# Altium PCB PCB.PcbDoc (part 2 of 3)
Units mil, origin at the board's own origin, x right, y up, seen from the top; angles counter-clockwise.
Board outline 3613 x 4415 mil, 2 copper layers (Top Layer, Bottom Layer), stack 62 mil thick; 332 components, 200 nets, 890 pads, 1069 vias.
Unrouted connection lines stored in the file: 1.
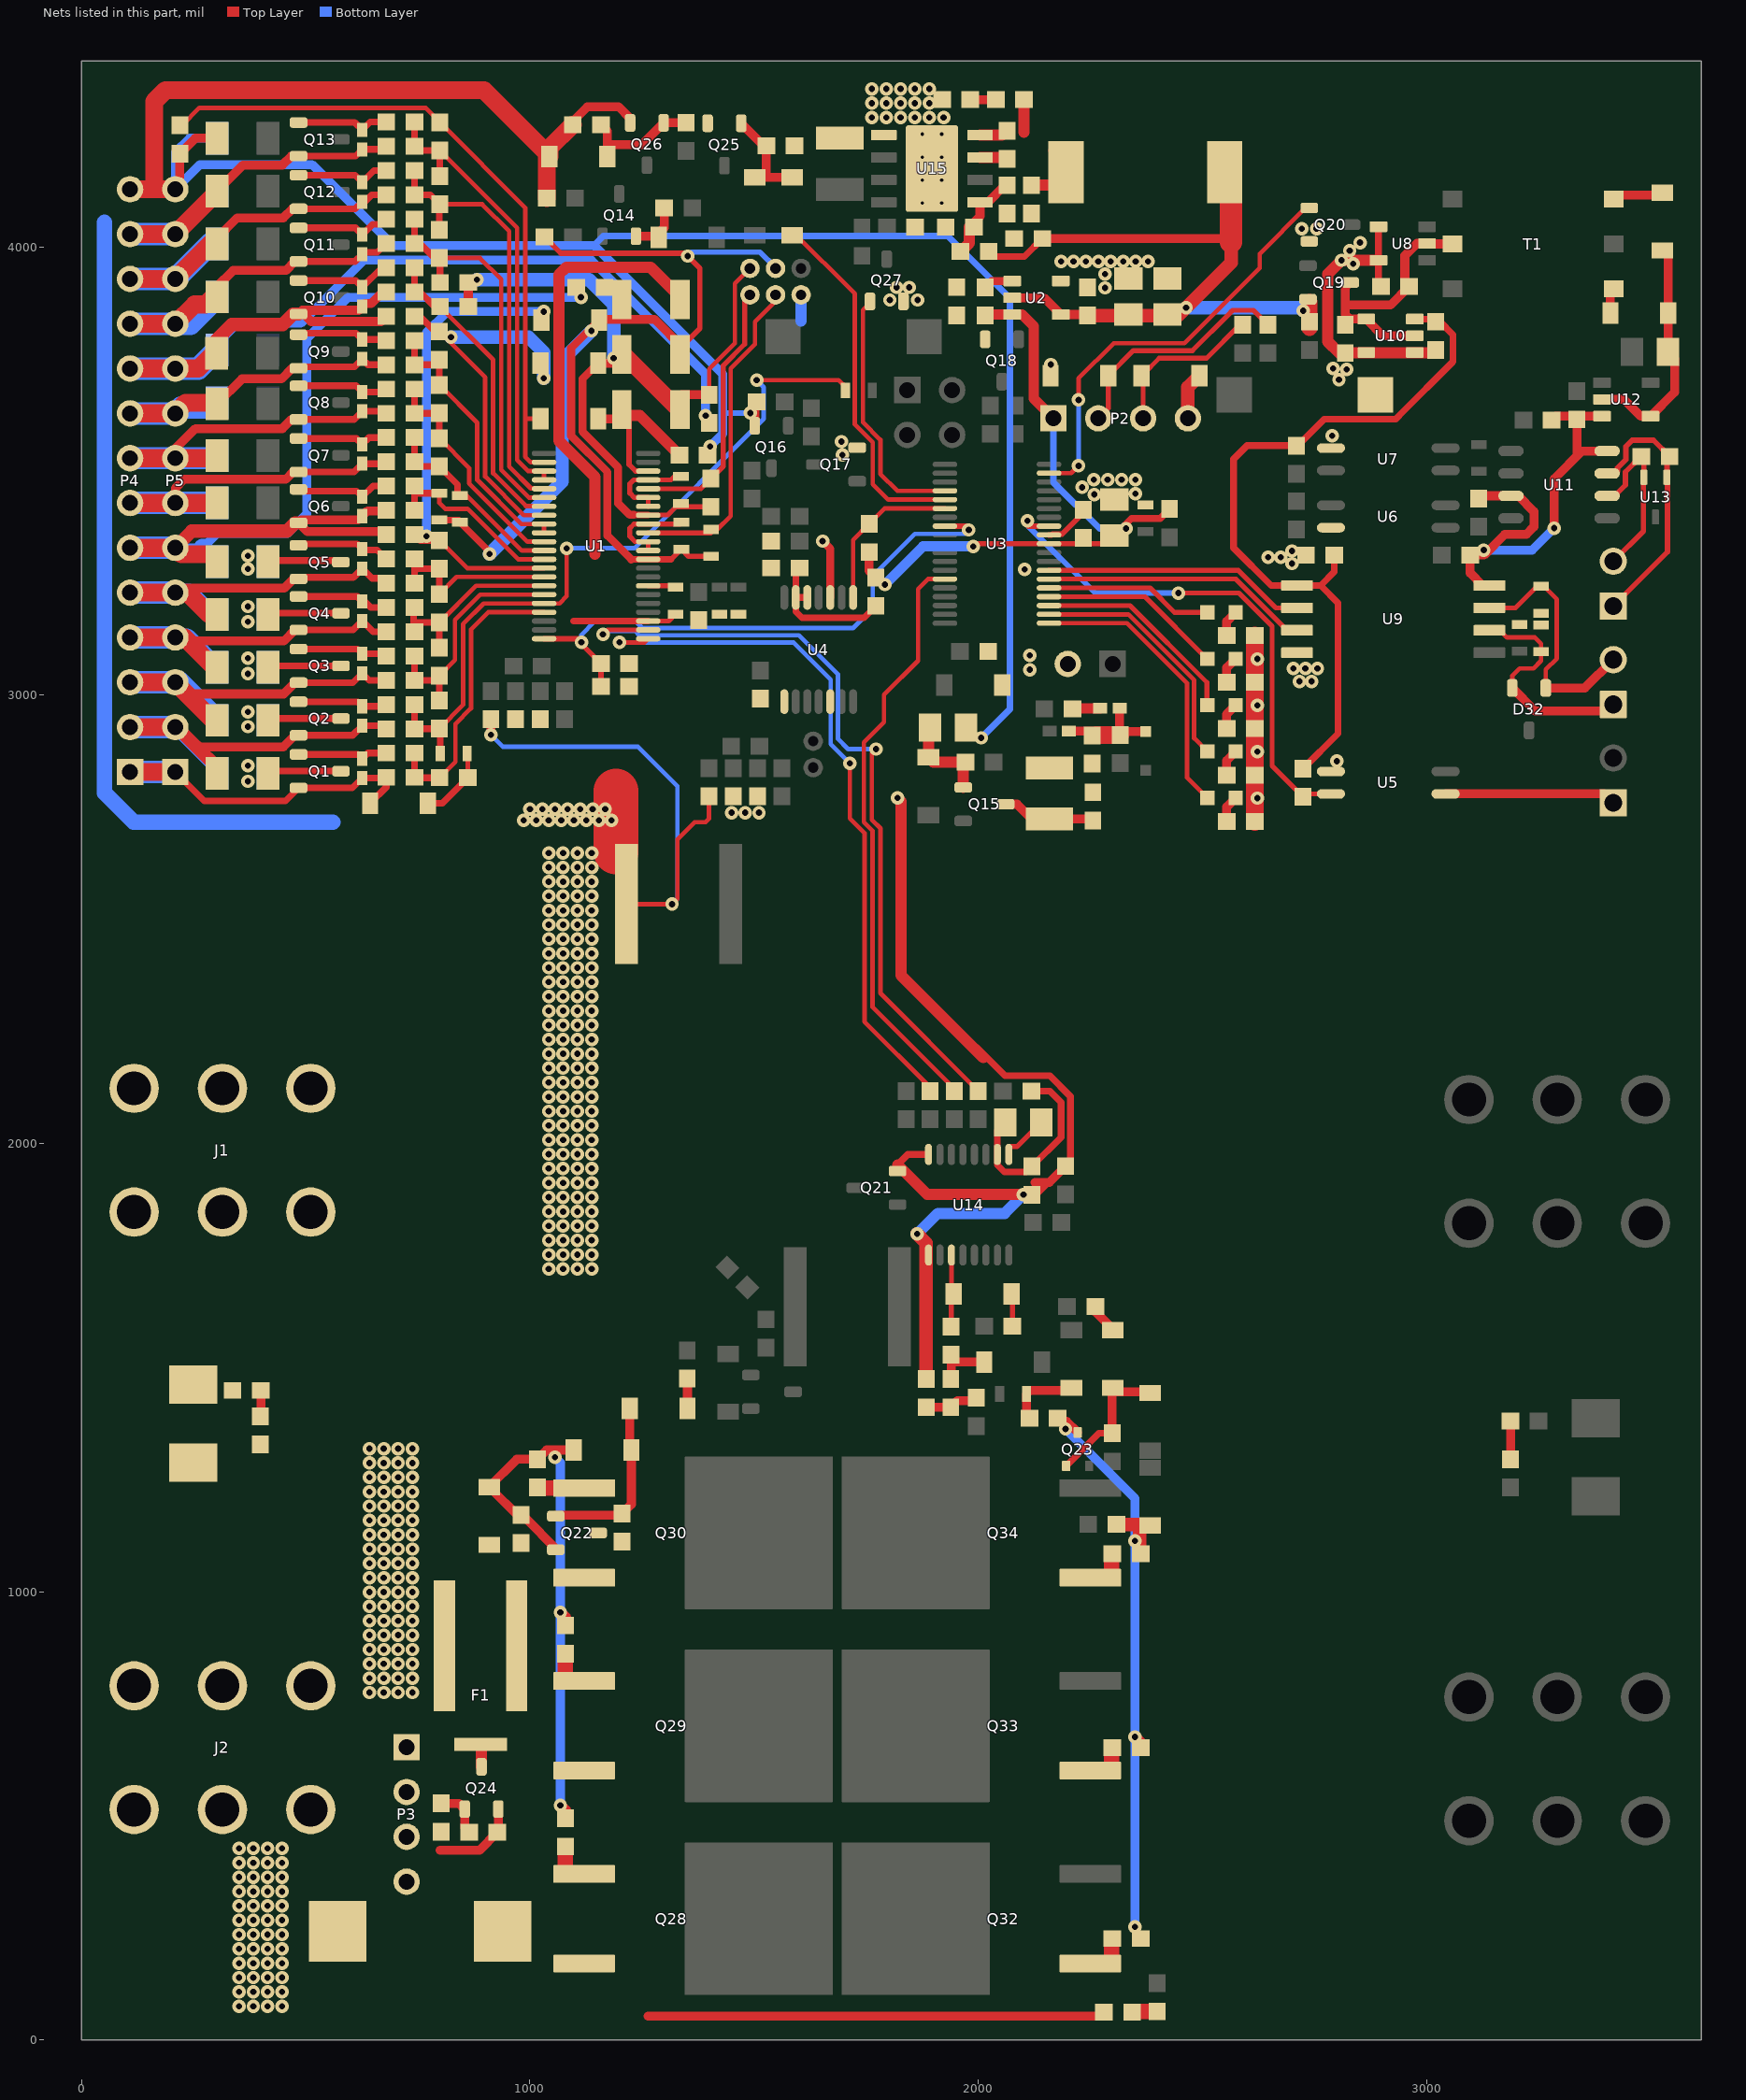
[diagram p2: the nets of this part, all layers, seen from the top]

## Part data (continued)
R11 R12 R13 R14 R15 R16 R30 R31 R32 R33 R34 R50 R51 R52 R53 R54 R63 R64 R65 R95 R96 R97 R99: "RES, 1.00 k, 1%, 0.1 W, 0603", Manufacturer=Vishay-Dale, Power_W=0.1, Supplier Part Number 1=541-1.00KHCT-ND, TempCo="100 ppm/C", Tolerance_%=1, Value1=1%, Value2=0.1W, Value_Code=1k00, ValueDisplayed=1.00k
R17 R18 R19 R20 R21 R35 R36 R37 R38 R55 R56 R57 R58 R66: "RES, 10 k, 5%, 0.1 W, 0603", Manufacturer=Vishay-Dale, Power_W=0.1, Supplier Part Number 1=541-10KGCT-ND, TempCo="200 ppm/C", Tolerance_%=5, Value1=5%, Value2=0.1W, Value_Code=10k0, ValueDisplayed=10k
R47 R49 R87: "RES, 100 k, 1%, 0.1 W, 0603", Manufacturer=Vishay-Dale, Power_W=0.1, Supplier Part Number 1=541-100KHCT-ND, TempCo="100 ppm/C", Tolerance_%=1, Value1=1%, Value2=0.1W, Value_Code=100k
R48 R100: "RES, 200, 1%, 0.1 W, 0603", Manufacturer=Vishay-Dale, Power_W=0.1, Supplier Part Number 1=541-200HCT-ND, TempCo="100 ppm/C", Tolerance_%=1, Value1=1%, Value2=0.1W, Value_Code=200R, ValueDisplayed=200
R59 R69 R106 R112: "RES, 1.0 M, 5%, 0.1 W, 0603", Manufacturer=Vishay-Dale, Power_W=0.1, Supplier Part Number 1=541-1.0MGCT-ND, TempCo="200 ppm/C", Tolerance_%=5, Value1=5%, Value2=0.1W, Value_Code=1M00, ValueDisplayed=1.0M
R60: "RES, 499 k, 1%, 0.1 W, 0603", Manufacturer=Vishay-Dale, Power_W=0.1, Supplier Part Number 1=541-499KHCT-ND, TempCo="100 ppm/C", Tolerance_%=1, Value1=1%, Value2=0.1W, Value_Code=499k
R61 R84 R85 R98 R107 R108 R111 R113 R117 R120 R124 R127: "RES, 100, 1%, 0.1 W, 0603", Manufacturer=Vishay-Dale, Power_W=0.1, Supplier Part Number 1=541-100HCT-ND, TempCo="100 ppm/C", Tolerance_%=1, Value1=1%, Value2=0.1W, Value_Code=100R, ValueDisplayed=100
R62 R103 R105 R110 R114 R121: "RES, 10 M, 5%, 0.1 W, 0603", Manufacturer=Vishay-Dale, Power_W=0.1, Supplier Part Number 1=541-10MGCT-ND, TempCo="200 ppm/C", Tolerance_%=5, Value1=5%, Value2=0.1W, Value_Code=10M0, ValueDisplayed=10M
R67: "RES, 360 k, 1%, 0.1 W, AEC-Q200 Grade 0, 0603", Manufacturer=Panasonic, Power_W=0.1, Supplier Part Number 1=P360KHCT-ND, TempCo="100 ppm/C", Tolerance_%=1, Value1=1%, Value2=0.1W, Value_Code=360k
R68: "RES, 3.01 k, 1%, 0.1 W, 0603", Manufacturer=Vishay-Dale, Power_W=0.1, Supplier Part Number 1=541-3.01KHCT-ND, TempCo="100 ppm/C", Tolerance_%=1, Value1=1%, Value2=0.1W, Value_Code=3k01, ValueDisplayed=3.01k
R70 R104: "RES, 3.3 M, 5%, 0.1 W, 0603", Manufacturer=Vishay-Dale, Power_W=0.1, Supplier Part Number 1=541-3.3MGCT-ND, TempCo="200 ppm/C", Tolerance_%=5, Value1=5%, Value2=0.1W, Value_Code=3M30, ValueDisplayed=3.3M
R71 R72: "RES, 505 k, 0.1%, 0.1 W, 0603", Manufacturer="Yageo America", Power_W=0.1, TempCo="25 ppm/C", Value1=0.1%, Value2=0.1W, Value_Code=505k
R73 R102: "RES, 16.5 k, 0.1%, 0.1 W, 0603", Manufacturer="Yageo America", Power_W=0.1, TempCo="25 ppm/C", Value1=0.1%, Value2=0.1W, Value_Code=16k5, ValueDisplayed=16.5k
R74 R115: "RES, 47.0, 1%, 0.1 W, 0603", Manufacturer="Yageo America", Power_W=0.1, Supplier Part Number 1=311-47.0HRCT-ND, TempCo="200 ppm/C", Tolerance_%=1, Value1=1%, Value2=0.1W, Value_Code=47R0, ValueDisplayed=47.0
R75 R81 R83 R88 R89 R90 R91: "RES, 10.0 k, 1%, 0.1 W, 0603", Manufacturer=Vishay-Dale, Power_W=0.1, Supplier Part Number 1=541-10.0KHCT-ND, TempCo="100 ppm/C", Tolerance_%=1, Value1=1%, Value2=0.1W, Value_Code=10k0, ValueDisplayed=10.0k
R76 R77 R78 R79 R80: "RES, 470, 1%, 0.1 W, 0603", Manufacturer="Yageo America", Power_W=0.1, Supplier Part Number 1=311-470HRCT-ND, TempCo="200 ppm/C", Tolerance_%=1, Value1=1%, Value2=0.1W, Value_Code=470R, ValueDisplayed=470
R82: "RES, 47.0 k, 1%, 0.1 W, 0603", Manufacturer="Yageo America", Power_W=0.1, Supplier Part Number 1=311-47.0KHRCT-ND, TempCo="200 ppm/C", Tolerance_%=1, Value1=1%, Value2=0.1W, Value_Code=47k0, ValueDisplayed=47.0k
R86: "RES, 6.8 k, 5%, 0.1 W, 0603", Manufacturer=Vishay-Dale, Power_W=0.1, Supplier Part Number 1=541-6.8KGCT-ND, TempCo="200 ppm/C", Tolerance_%=5, Value1=5%, Value2=0.1W, Value_Code=6k80, ValueDisplayed=6.8k
R92 R93: "RES, 60.4, 1%, 0.1 W, 0603", Manufacturer="Yageo America", Power_W=0.1, Supplier Part Number 1=311-60.4HRCT-ND, TempCo="200 ppm/C", Tolerance_%=1, Value1=1%, Value2=0.1W, Value_Code=60R4, ValueDisplayed=60.4
R94: "RES, 120, 1%, 0.1 W, 0603", Manufacturer="Yageo America", Power_W=0.1, Supplier Part Number 1=311-120HRCT-ND, TempCo="200 ppm/C", Tolerance_%=1, Value1=1%, Value2=0.1W, Value_Code=120R, ValueDisplayed=120
R101: "RES, 665 k, 0.1%, 0.1 W, 0603", Manufacturer="Yageo America", Power_W=0.1, TempCo="25 ppm/C", Value1=0.1%, Value2=0.1W, Value_Code=665k
R109: "RES, 510, 5%, 0.1 W, 0603", Manufacturer=Vishay-Dale, Power_W=0.1, Supplier Part Number 1=541-510GCT-ND, TempCo="200 ppm/C", Tolerance_%=5, Value1=5%, Value2=0.1W, Value_Code=510R, ValueDisplayed=510
R116: "RES, 2.49 M, 1%, 0.1 W, 0603", Manufacturer=Vishay-Dale, Power_W=0.1, Supplier Part Number 1=541-2.49MHCT-ND, TempCo="100 ppm/C", Tolerance_%=1, Value1=1%, Value2=0.1W, Value_Code=2M49, ValueDisplayed=2.49M
R118 R119: "RES, 0.002, 1%, 2 W, 2512", Manufacturer="Stackpole Electronics Inc", Power_W=2, Supplier Part Number 1=CSNL2512FT2L00CT-ND, TempCo="50 ppm/C", Tolerance_%=1, Value1=1%, Value2=2W, Value_Code=2L000, ValueDisplayed=0.002
R122: "RES, 6.8 M, 5%, 0.1 W, 0603", Manufacturer=Vishay-Dale, Power_W=0.1, Supplier Part Number 1=541-6.8MGCT-ND, TempCo="200 ppm/C", Tolerance_%=5, Value1=5%, Value2=0.1W, Value_Code=6M80, ValueDisplayed=6.8M
R123: "RES, 3.0 M, 5%, 0.1 W, 0603", Manufacturer=Vishay-Dale, Power_W=0.1, Supplier Part Number 1=541-3.0MGCT-ND, TempCo="200 ppm/C", Tolerance_%=5, Value1=5%, Value2=0.1W, Value_Code=3M00, ValueDisplayed=3.0M
R125: "RES, 1.00 M, 1%, 0.1 W, 0603", Manufacturer=Vishay-Dale, Power_W=0.1, Supplier Part Number 1=541-1.00MHCT-ND, TempCo="100 ppm/C", Tolerance_%=1, Value1=1%, Value2=0.1W, Value_Code=1M00, ValueDisplayed=1.00M
R126: "RES, 115 k, 1%, 0.1 W, 0603", Manufacturer=Vishay-Dale, Power_W=0.1, Supplier Part Number 1=541-115KHCT-ND, TempCo="100 ppm/C", Tolerance_%=1, Value1=1%, Value2=0.1W, Value_Code=115k
R128: "NC", Manufacturer="Yageo America", Power_W=0.1, Supplier Part Number 1=311-383KHRCT-ND, TempCo="200 ppm/C", Tolerance_%=1, Value1=1%, Value2=0.1W, Value_Code=383k
R129: "RES, 383 k, 1%, 0.1 W, 0603", Manufacturer="Yageo America", Power_W=0.1, Supplier Part Number 1=311-383KHRCT-ND, TempCo="200 ppm/C", Tolerance_%=1, Value1=1%, Value2=0.1W, Value_Code=383k
R130: "RES, 240 k, 5%, 0.1 W, 0603", Manufacturer=Vishay-Dale, Power_W=0.1, Supplier Part Number 1=541-240KGCT-ND, TempCo="200 ppm/C", Tolerance_%=5, Value1=5%, Value2=0.1W, Value_Code=240k
R131: "RES, 715 k, 1%, 0.1 W, 0603", Manufacturer=Vishay-Dale, Power_W=0.1, Supplier Part Number 1=541-715KHCT-ND, TempCo="100 ppm/C", Tolerance_%=1, Value1=1%, Value2=0.1W, Value_Code=715k
R132 R133: "RES, 604, 1%, 1 W, AEC-Q200 Grade 0, 2512", Manufacturer=Vishay-Dale, Power_W=1, Supplier Part Number 1=541-604AFCT-ND, TempCo="100 ppm/C", Value1=1%, Value2=1W, Value_Code=604R, ValueDisplayed=604
RT1 RT2 RT3 RT4: "Thermistor NTC, 10k ohm, 2%, NTC Thermistor, Mini Lug Sensor, Pitch 1.5mm", Manufacturer=Vishay-Bccomponents, Power_W=0.1, Supplier Part Number 1=BC2385-ND, Tolerance_%=2
S1 S2: "Switch, Tactile, SPST-NO, 0.05A, 12V, SMD", CurrentRating_mA=50, Manufacturer="C&K Components", Supplier Part Number 1=CKN10388CT-ND
T1: "Transformer, 475 uH, SMT", Manufacturer="Wurth Elektronik", Supplier Part Number 1=732-4456-1-ND, ValueDisplayed=475μH
U1: library part CMP-0065910-1, "9 to 15-Series Cell Li-Ion and Li-Phosphate Battery Monitor (bq76940 Family), DBT0044A (TSSOP-44)", Alternate Manufacturer="Texas Instruments", Alternate PartNumber=BQ7694003DBT
U2 U10: "Single Output LDO, 150 mA, Fixed 3.3 V Output, 2.5 to 24 V Input, with Ultra-Low IQ, 5-pin SOT-23 (DBV), -40 to 125 degC, Green (RoHS & no Sb/Br)", Alternate Manufacturer="Texas Instruments", Alternate PartNumber=Equivalent, Supplier Part Number 1=TLV70433DBVR-ND
U3: library part CMP-0084060-1, "24MHz 105C ULP Microcontroller With 32 KB FRAM, 4 KB SRAM, 44 IO, 12-bit ADC, DBT0038A (TSSOP-38)", Alternate Manufacturer="Texas Instruments", Alternate PartNumber=MSP430FR2155TDBT, Operating Temperature Range="-40 to 105 C", Rating=Catalog
U4: library part CMP-0082025-1, "Multi-Chemistry Impedance Track Standalone Fuel Gauge", Alternate Manufacturer="Texas Instruments", Alternate PartNumber=BQ34Z100PW-G1, Operating Temperature Range="-40 to 85 C"
U5 U6 U7: "Optocoupler, 3.75 kV, 100-600% CTR, SMT", Manufacturer=Toshiba, Supplier Part Number 1=TLP293(GB-TPLECT-ND, Voltage_Isolation_Vrms=3750V
U8: library part CMP-0065840-1, "Low-Noise 350 mA, 410 kHz Transformer Driver, DBV0005A (SOT-23-5)", Alternate Manufacturer="Texas Instruments", Alternate PartNumber=SN6501DBVT
U9: library part CMP-0077952-1, "Reinforced Isolated CAN XCVRs with 70V Protection Voltage and CAN FD, DWV0008A (SOIC-8)", Alternate Manufacturer="Texas Instruments", Alternate PartNumber=ISO1042BDWV
U11: library part CMP-0013008-2, "250 kbps RS-485 Transceivers With +/-12-kV IEC ESD Protection, D0008A (SOIC-8)", Alternate Manufacturer="Texas Instruments", Alternate PartNumber=THVD1500D
U12: "Single Output LDO, 150 mA, Fixed 5 V Output, 2.5 to 24 V Input, with Ultra-Low IQ, 5-pin SOT-23 (DBV), -40 to 125 degC, Green (RoHS & no Sb/Br)", Alternate Manufacturer="Texas Instruments", Alternate PartNumber=Equivalent, Supplier Part Number 1=296-28171-2-ND
U13: "ESD Protection Array for AC Signal Data Interface, 2 Channels, -40 to +85 degC, 3-pin SC70 (DCK), Green (RoHS & no Sb/Br)", Alternate Manufacturer="Texas Instruments", Alternate PartNumber=Equivalent, Breakdown Voltage(Min)(V)=+/-14, IO Capacitance(Typ)(pF)=15, IO Leakage Current(nA)=50, Supplier Part Number 1=296-25281-2-ND
U14: library part CMP-0076175-1, "High-Side N-Channel FET Driver, PW0016A (TSSOP-16)", Alternate Manufacturer="Texas Instruments", Alternate PartNumber=BQ76200PW
U15: library part CMP-0080798-1, "100-V Low IQ Synchronous Buck Regulator, DDA0008E (SOIC-8)", Alternate Manufacturer="Texas Instruments"

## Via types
v1: diameter 30, hole 14, Top Layer to Bottom Layer, 1060 vias
v2: diameter 19.68, hole 7.87, Top Layer to Bottom Layer, tented both sides, 4 vias
v3: diameter 19.68, hole 7.87, Top Layer to Bottom Layer, 4 vias
v4: diameter 30, hole 14, Top Layer to Bottom Layer, tented bottom, 1 vias

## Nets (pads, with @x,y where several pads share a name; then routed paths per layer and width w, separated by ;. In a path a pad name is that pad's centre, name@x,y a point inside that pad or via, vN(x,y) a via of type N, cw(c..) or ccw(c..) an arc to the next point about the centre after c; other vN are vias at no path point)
3V3: C31.2 C33.2 C34.1 C35.1 P2.1 Q18.2 R74.1 R75.1 R82.2 U2.3 U3.10 | length 1424.5
  Top Layer w12: v1@1992,3338 U3.10@2158.14,3338 C31.2@2285.55,3338
  Top Layer w15: C31.2@2304,3356.45 2342.18,3394.63 2406.13,3394.63 R82.2@2427,3415.5
  Top Layer w20: R75.1@1757,3319.5 1757,3277.5 R74.1@1772,3262.5
  Top Layer w23: C34.1@2018.24,3849.6 U2.3@2076,3849.6 2098,3849.6 2124,3823.6 2124,3662 P2.1@2168,3618
  Bottom Layer w15: P2.1@2168,3618 2168,3475 2271,3372 v1(2330,3372)
  Bottom Layer w23: v1(1792,3247) 1877,3332 v1(1989,3332)
3V3_Com: C39.2 C44.1 R88.2 R89.2 U9.1 U10.3 | length 1695.2
  Top Layer w15: R89.2@2725,2836.5 2803,2914.5 2803,3206 2764,3245 ; C39.2@2794.5,3313 2794.5,3275.5 2764,3245 ; U10.3@2974.13,3839.4 C44.1@3015.09,3839.4 ; C44.1@3021,3833.5 3030.5,3833.5 3059,3805 3059,3744 2939.35,3624.35 2939.35,3624.04 2931.44,3616.13 2931.13,3616.13 2931,3616 2772,3616 2713,3557 R88.2@2710,3557 2600,3557 2570,3527 2570,3329 2654,3245 U9.1@2711.43,3245 2764,3245
5V: C32.1 C65.2 C66.1 C67.1 L1.2 Q19.2 R87.1 R131.2 U2.2 U2.4 | length 1622.8
  Top Layer w15: R131.2@2034.5,3979 2103.5,3979 C65.2@2143.5,4019
  Top Layer w20: U2.2@2076,3887 2146.87,3887 U2.4@2184.27,3849.6 2241.54,3849.6 C32.1@2244,3847.14 ; C65.2@2143.5,4019 2556.54,4019
  Top Layer w30: C32.1@2244,3847.14 2446.14,3847.14 v1(2464,3865) 2564.27,3965.27 2564.27,4011.27
  Top Layer w35: R87.1@2739,3819 R87.1@2739,3833.5 Q19.2@2739,3878
  Top Layer w50: L1.2@2550.17,4167 2564.27,4152.89 2564.27,4011.27
  Bottom Layer w30: v1(2464,3865) 2718,3865 v1(2725,3858)
5V_S: C41.1 C43.1 C47.1 R90.2 U9.8 U11.3 U11.8 U12.3 | length 1062.2
  Top Layer w20: R90.2@3117,3439 3123,3445 U11.3@3188.72,3445 3205,3445 3240,3410 3240,3376 3223,3359 3175,3359 3129,3313 C43.1@3097.5,3313 3097.5,3272.61 3125.11,3245 U9.8@3140.57,3245 ; C41.1@3279.5,3614 3288.09,3622.6 U12.3@3391.87,3622.6 ; v1(3285,3373) 3285,3483 3347,3545 U11.8@3403.28,3545 ; 3336,3538 C47.1@3336,3615.5
  Bottom Layer w20: v1(3128,3324) 3236,3324 v1(3285,3373)
430_Power: D45.2 U3.24 | length 833.7
  Top Layer w10: D45.2@1585,4017 1585,4035.88 1725,3895.88 1725,3604 1754.32,3574.69 1754.6,3574.69 1765,3564.28 1765,3471 1799.57,3436.43 U3.24@1925.86,3436.43
485A: J3.2 R94.2 U11.6 U13.2 | length 385.6
  Top Layer w12: U11.6@3403.28,3445 3420.02,3445 3444.05,3469.03 3444.05,3498.05 3479,3533 R94.2@3479.5,3533 ; J3.2@3417,3299 3484,3366 3484,3484.88 U13.2@3485.41,3486.29 R94.2@3485.41,3526.59
485B: J3.1 R94.1 U11.7 U13.1 | length 585.2
  Top Layer w12: U11.7@3403.28,3495 3422,3495 3426.05,3499.05 3426.05,3507.05 3445,3526 3445,3555 3459,3569 3506.5,3569 R94.1@3542.5,3533 ; J3.1@3417,3199 3538,3320 3538,3484.88 U13.1@3536.59,3486.29 R94.1@3536.59,3527.09
ALERT: C19.1 R60.2 U1.44 U3.27 | length 1295.6
  Top Layer w12: U1.44@1031.69,3126.18 1106.82,3126.18 v1(1115,3118) 1115,3114.5 C19.1@1158.5,3071 R60.2@1158.5,3020 ; U3.27@1925.86,3377.37 1976.37,3377.37 1977,3378 1979,3376 v1(1979,3369)
  Bottom Layer w10: v1(1115,3118) 1115,3135 1144,3164 1236.63,3164 1250.63,3150 1721,3150 1765,3194 1765,3266 1859,3360 1970,3360 v1(1979,3369)
Alert_Gauge: R75.2 U3.25 U4.1 | length 362.2
  Top Layer w10: U4.1@1721.17,3218.17 1721.17,3346.67 R75.2@1757,3382.5 1791.24,3416.74 U3.25@1925.86,3416.74
BAT: C26.2 D20.1 R65.2 U1.20 | length 365.6
  Top Layer w12: C26.2@1221,3621.04 1221,3515 1235.81,3500.19 U1.20@1263.98,3500.19
  Top Layer w20: D20.1@1152.47,3617 C26.2@1208.91,3617
  Top Layer w25: C26.2@1216,3624.09 1245.42,3624.09 R65.2@1333.5,3536
BAT+: C53.1 D44.1 F1.1 F2.2 J2.1 J2.2 J2.3 J2.4 J2.5 J2.6
  other v1: 351,75 383,75 415,75 447,75 351,107 383,107 415,107 447,107 351,139 383,139 415,139 447,139 351,171 383,171 415,171 447,171 351,203 383,203 415,203 447,203 351,235 383,235 415,235 447,235 351,267 383,267 415,267 447,267 351,299 383,299 415,299 447,299 351,331 383,331 415,331 447,331 351,363 383,363 415,363 447,363 351,395 383,395 415,395 447,395 351,427 383,427 415,427 447,427 642,775 674,775 706,775 738,775 642,807 674,807 706,807 738,807 642,839 674,839 706,839 738,839 642,871 674,871 706,871 738,871 642,903 674,903 706,903 738,903 642,935 674,935 706,935 738,935 642,967 674,967 706,967 738,967 642,999 674,999 706,999 738,999 642,1031 674,1031 706,1031 738,1031 642,1063 674,1063 706,1063 738,1063 642,1095 674,1095 706,1095 738,1095 642,1127 674,1127 706,1127 738,1127 642,1159 674,1159 706,1159 738,1159 642,1191 674,1191 706,1191 738,1191 642,1223 674,1223 706,1223 738,1223 642,1255 674,1255 706,1255 738,1255 642,1287 674,1287 706,1287 738,1287 642,1319 674,1319 706,1319 738,1319
C0: C1.1 R11.2 R17.2 U1.41 | length 649.3
  Top Layer w10: C1.1@798.5,2816 834,2851.5 834,2936.23 868.75,2970.97 868.75,3146.75 907.23,3185.23 U1.41@1031.69,3185.23
  Top Layer w15: R17.2@742.5,2871.05 R11.2@742.5,2816.91 743.41,2816 C1.1@798.5,2816
C1: C2.1 C3.2 R12.2 R18.2 R68.2 U1.40 | length 1645.1
  Top Layer w10: C3.2@798,2925.5 850.87,2978.38 850.87,3158.87 896.92,3204.92 U1.40@1031.69,3204.92 1065.92,3204.92 1082,3221 v1(1082,3328) ; v1(1506,3703) 1689,3703 R68.2@1704,3688
  Top Layer w15: R18.2@742.5,2979.35 R12.2@742.5,2925.2 798.3,2925.2 800,2923.5 C2.1@800,2870
  Bottom Layer w10: v1@1082,3324 v1(1082,3328) 1233,3328 1521.5,3616.5 1521.5,3687.5 v1(1506,3703)
C2: C3.1 C4.2 R13.2 R19.2 U1.39 | length 529.9
  Top Layer w10: C4.2@798,3043.5 833,3078.5 833,3168 889.6,3224.6 U1.39@1031.69,3224.6
  Top Layer w15: R19.2@742.5,3087.65 R13.2@742.5,3033.5 788,3033.5 C4.2@798,3043.5 C3.1@798,2988.5
C3: C4.1 C5.2 R14.2 R20.2 U1.38 | length 412.5
  Top Layer w10: C5.2@798,3162.5 879.78,3244.29 U1.38@1031.69,3244.29
  Top Layer w15: R20.2@740.5,3193.94 740.5,3162.5 C5.2@798,3162.5 C4.1@798,3106.5
C4: C5.1 C6.2 R15.2 R21.2 U1.37 | length 418.8
  Top Layer w10: C5.1@798,3225.5 836.48,3263.97 U1.37@1031.69,3263.97
  Top Layer w15: R15.2@742.5,3250.09 742.5,3276.5 ; R21.2@742.5,3304.24 742.5,3276.5 ; C5.1@798,3225.5 C6.2@798,3282.5 748.5,3282.5 742.5,3276.5
C5: C6.1 D17.2 R16.2 U1.36 | length 1062
  Top Layer w10: C6.1@798,3345.5 859.84,3283.66 U1.36@1031.69,3283.66
  Top Layer w15: R16.2@742.5,3358.39 755.39,3345.5 C6.1@798,3345.5
  Top Layer w20: C6.1@798,3345.5 C6.1@802.5,3350
  Bottom Layer w20: v1(769,3355) 769,3809 814,3854 816,3856 v1(1031,3856)
C5B: C7.1 R30.2 R35.2 U1.35 | length 400.5
  Top Layer w10: C7.1@798,3451 798,3429 811,3416 861,3416 973.66,3303.34 U1.35@1031.69,3303.34
  Top Layer w15: R30.2@742.5,3412.54 742.5,3449 744.5,3451 C7.1@798,3451
C5X: C7.2 C8.2 C23.2 C24.2 C25.1 C27.2 D17.1 R47.1 R63.2 RT2.2 U1.10 | length 2545.3
  Top Layer w11: 1315.34,3303.34 C23.2@1338,3326
  Top Layer w12: R47.1@1032.81,4022.42 1069.23,3986 1264.53,3986 1310.51,3985.98 ; 1310.53,3986 1346,3986 v1(1352,3980) 1379,3953 1379,3818.18 1375,3814.18 1375,3814 C25.1@1343.09,3782.09 ; C23.2@1338,3326 1354,3310 C27.2@1404,3310
  Top Layer w15: C7.2@798,3391 C8.2@842,3391 ; C8.2@844,3386 v1@910,3320 ; 1226.19,3303.34 U1.10@1263.98,3303.34 1315.34,3303.34
  Top Layer w18: D17.1@1154.47,3837 1092,3774.53 1092,3579 1173,3498 1173,3356.54 1226.19,3303.34
  Top Layer w20: D17.1@1154.47,3837 1156.47,3839 1278,3839 1343.09,3773.91 C25.1@1343.09,3760
  Bottom Layer w12: v1(1352,3980) 1361,3989 1513.36,3989 1548,3954.36 RT2.2@1548,3952.53
  Bottom Layer w30: v1(910,3315) 1072,3477 1072,3748 v1(1137,3813)
C6: C8.1 C9.2 R31.2 R36.2 U1.34 | length 421.1
  Top Layer w10: C8.1@859,3446 981.97,3323.03 U1.34@1031.69,3323.03
  Top Layer w15: R36.2@742.5,3574.98 R31.2@742.5,3520.83 752.83,3510.5 C9.2@798,3510.5 838.5,3470 838.5,3451.5 C8.1@844,3446
C7: C9.1 C10.2 R32.2 R37.2 U1.33 | length 513.7
  Top Layer w10: C9.1@798,3573.5 864.44,3507.05 864.44,3473.16 994.89,3342.71 U1.33@1031.69,3342.71
  Top Layer w15: R37.2@742.5,3683.28 R32.2@742.5,3629.13 797.62,3629.13 C9.1@797.62,3573.87
C8: C10.1 C11.2 R33.2 R38.2 U1.31 U1.32 | length 627
  Top Layer w10: C10.1@798,3692.5 882.32,3608.18 882.32,3480.56 980.8,3382.08 U1.31@1031.69,3382.08 U1.32@1031.69,3362.4
  Top Layer w15: R38.2@742.5,3791.57 R33.2@742.5,3737.42 786.92,3737.42 C11.2@798,3748.5 C10.1@798,3692.5
C9: C11.1 D18.2 R34.2 U1.30 | length 872.3
  Top Layer w10: C11.1@798,3811.5 900.19,3709.3 900.19,3487.96 986.39,3401.77 U1.30@1031.69,3401.77
  Top Layer w15: R34.2@742.5,3845.72 754.28,3845.72 C11.1@788.5,3811.5
  Bottom Layer w30: v1(824,3799) 997,3799 1031,3765 v1(1031,3707)
C10: C14.1 C15.2 R51.2 R56.2 U1.28 | length 882.5
  Top Layer w10: C15.2@798,3975.5 888.5,3975.5 935.94,3928.06 935.94,3502.77 997.57,3441.14 U1.28@1031.69,3441.14
  Top Layer w15: R56.2@742.5,4062.31 R51.2@742.5,4008.16 754.84,4008.16 789,3974 799.5,3974 C14.1@799.5,3921
C10B: C12.1 R50.2 R55.2 U1.29 | length 690.3
  Top Layer w10: C12.1@799.5,3867 918.07,3748.44 918.07,3495.37 991.08,3422.36 1031.69,3422.36 U1.29@1031.69,3421.45
  Top Layer w15: R55.2@742.5,3954.02 R50.2@742.5,3899.87 755.13,3899.87 788,3867 C12.1@799.5,3867
C10X: C12.2 C14.2 C22.2 C25.2 C26.1 C28.2 D18.1 R64.2 RT3.2 U1.15 | length 1702.6
  Top Layer w10: R64.2@1400,3670.5 1400,3727.67 1457.35,3785.02 1457.35,3918.87 RT3.2@1491,3952.53
  Top Layer w11: U1.15@1264.38,3402.17 1307.76,3402.17 1326.09,3420.5 C28.2@1404,3420.5
  Top Layer w15: 1234.07,3402.05 U1.15@1263.98,3402.05
  Top Layer w18: D18.1@1152.47,3741 1117.13,3705.66 1117.13,3588.17 1197,3508.3 1197,3428 1222.42,3402.58 1231.63,3402.58
  Top Layer w20: C12.2@862.5,3867 C14.2@862.5,3921 ; D18.1@1152.47,3741 C25.2@1205.04,3741 ; C26.1@1338.5,3670.5 R64.2@1400,3670.5
  Top Layer w38: C25.2@1205.04,3760 1210,3760 1333,3637 C26.1@1334.96,3637 C26.1@1334.96,3640.04
  Bottom Layer w30: v1(882,3927) 1132.23,3927 1187,3872.23 v1(1187,3752)
C11: C15.1 C16.2 R52.2 R57.2 U1.27 | length 978.6
  Top Layer w10: C16.2@799,4095.5 893.72,4095.5 953.81,4035.41 953.81,3510.17 1002.26,3461.73 1030.79,3461.73 U1.27@1031.69,3460.82
  Top Layer w15: R57.2@742.5,4170.61 R52.2@742.5,4116.46 778.04,4116.46 C16.2@799,4095.5 ; C15.1@798,4038.5 C16.2@798,4094.5
C12: C16.1 C17.2 R53.2 R58.2 U1.25 U1.26 | length 1023.6
  Top Layer w10: C17.2@799,4215.5 971.69,4042.82 971.69,3524.76 996.25,3500.19 U1.25@1031.69,3500.19 U1.26@1031.69,3480.51
  Top Layer w15: R58.2@742.5,4278.91 R53.2@742.5,4224.76 751.76,4215.5 C17.2@799,4215.5 C16.1@799,4158.5
C13: C17.1 D20.2 R54.2 U1.24 | length 1510.6
  Top Layer w10: R54.2@224,4271.5 262.98,4310.48 767.52,4310.48 799,4279 C17.1@799,4278.5 989.56,4087.93 989.56,3532.16 1001.84,3519.88 U1.24@1031.69,3519.88
  Top Layer w11: 990.06,3617 D20.2@1023.53,3617
CAN_R: U3.6 U9.3 | length 600.6
  Top Layer w11: U3.6@2158.14,3259.26 2574.74,3259.26 2689,3145 U9.3@2711.43,3145
CAN_T: U3.7 U9.2 | length 588.1
  Top Layer w11: U3.7@2158.14,3278.94 2580.06,3278.94 2664,3195 U9.2@2711.43,3195
CANH: D32.1 J4.2 R93.1 U9.7 | length 566.6
  Top Layer w10: U9.7@3140.57,3195 3199,3195 R93.1@3247,3243 ; R93.1@3256,3243 3262,3243 3291,3214 3291,3082 3266.4,3057.4 D32.1@3266.4,3016.24
  Top Layer w20: D32.1@3266.4,3016.24 3353.74,3016.24 J4.2@3417,3079.5 J4.2@3408.5,3079.5
CANL: D32.2 J4.1 R92.2 U9.6 | length 524.1
  Top Layer w10: U9.6@3140.57,3145 3164,3145 3180,3129 3242,3129 3256,3115 R92.2@3256,3097 3256,3077 3239,3060 3208,3060 3191.6,3043.6 D32.2@3191.6,3016.24
  Top Layer w20: D32.2@3191.6,3016.24 3242.84,2965 3402.5,2965 J4.1@3417,2979.5
CAP1: C21.1 U1.7 | length 57.3
  Top Layer w11: U1.7@1263.98,3244.29 C21.1@1321.29,3244.29
CAP2: C23.1 U1.11 U1.12 U1.14 | length 198.9
  Top Layer w11: U1.11@1263.98,3323.03 U1.12@1263.98,3342.71 1263.57,3343.12 1234.34,3343.12 1223.04,3354.41 1223.04,3373.04 1232.08,3382.08 U1.14@1263.98,3382.08 C23.1@1334.08,3382.08
CAP3: C22.1 U1.16 U1.17 U1.19 | length 191.4
  Top Layer w11: U1.16@1263.98,3421.45 U1.17@1263.98,3441.14 1232.86,3441.14 1223,3451 1223,3472 1231.51,3480.51 U1.19@1263.98,3480.51 1314.51,3480.51 C22.1@1322,3488
Cell0: D1.1 D2.2 P4.1 P5.1 Q1.2 R11.1 | length 782.6
  Top Layer w15: P5.1@208.63,2828.78 273.4,2764 454.73,2764 Q1.2@484,2793.27 604.01,2793.27 D2.2@626,2815.25 R11.1@669,2815.25 ; D1.1@643.53,2759 679.51,2794.98 R11.1@679.51,2816.91
  Top Layer w40: P4.1@108,2829 P5.1@208.4,2829
  Bottom Layer w50: P4.1@108,2829 P5.1@209,2829
Cell1: D3.2 P4.2 P5.2 Q2.2 R1.2 R2.2 R12.1 | length 1022.5
  Top Layer w15: P4.2@108.22,2928.78 P5.2@208.63,2928.78 ; Q2.2@484,2910.75 604.59,2910.75 D3.2@626,2932.15 R12.1@672.57,2932.15
  Top Layer w20: 256.91,2884.09 257.82,2885 450.26,2885 476.01,2910.75 Q2.2@484,2910.75
  Top Layer w30: P5.2@209,2929 212,2929 256.91,2884.09 301.82,2839.18 R1.2@301.82,2826
  Top Layer w40: P4.2@108.22,2928.78 108.45,2929 P5.2@209,2929
  Bottom Layer w30: P5.2@209,2929 301.82,2836.18 R2.2@301.82,2826
  Bottom Layer w50: P4.2@108,2929 P5.2@209,2929
Cell2: D4.2 P4.3 P5.3 Q3.2 R3.2 R4.2 R13.1 | length 924.5
  Top Layer w15: R3.2@297.57,2948.34 R3.2@301.82,2944.08 ; Q3.2@484,3028.22 605.18,3028.22 D4.2@626,3049.04 641.54,3033.5 R13.1@679.51,3033.5
  Top Layer w20: 236,3003 450.79,3003 476.01,3028.22 Q3.2@484,3028.22
  Top Layer w40: P4.3@108,3029 208.4,3029 R3.2@293.32,2944.08
  Bottom Layer w50: P4.3@108,3029 P5.3@209,3029 216.91,3029 R4.2@301.82,2944.08
Cell3: D5.2 P4.4 P5.4 Q4.2 R5.2 R6.2 R14.1 | length 908.1
  Top Layer w15: Q4.2@484,3145.7 605.76,3145.7 D5.2@626,3165.94 650.14,3141.8 R14.1@679.51,3141.8
  Top Layer w20: P5.4@237.23,3121 451.31,3121 476.01,3145.7 Q4.2@484,3145.7
  Top Layer w40: P4.4@108,3129 P5.4@209,3129 229.23,3129 237.23,3121 R5.2@296.07,3062.17
  Bottom Layer w40: P5.4@209,3129 234.99,3129 R6.2@301.82,3062.17
  Bottom Layer w50: P4.4@108,3129 P5.4@209,3129
Cell4: D6.2 P4.5 P5.5 Q5.2 R7.2 R8.2 R15.1 | length 909.7
  Top Layer w15: R7.2@293.29,3188.79 R7.2@301.82,3180.25 ; Q5.2@484,3263.18 606.34,3263.18 D6.2@626,3282.84 647.83,3261 668.6,3261 R15.1@679.51,3250.09
  Top Layer w20: P5.5@219,3239 451.83,3239 472.43,3259.6 Q5.2@483.76,3259.6
  Top Layer w40: P4.5@108,3229 P5.5@209,3229 236,3229 R7.2@284.75,3180.25
  Bottom Layer w15: R8.2@295.29,3186.79 R8.2@301.82,3180.25
  Bottom Layer w40: P5.5@209,3229 240,3229 R8.2@288.75,3180.25
  Bottom Layer w50: P4.5@108,3229 P5.5@209,3229
Cell5: D7.2 P4.6 P5.6 Q6.2 R9.2 R10.2 R16.1 R30.1 R63.1 | length 2430
  Top Layer w20: R16.1@679.51,3358.39 679.51,3365 503.35,3365 Q6.2@483.76,3384.6 490.16,3391 617.26,3391 D7.2@626,3399.73 637.55,3411.29 679.51,3411.29 R30.1@679.51,3412.54
  Top Layer w30: P5.6@208.4,3329 245.4,3366 457.62,3366 476.22,3384.6 Q6.2@483.76,3384.6
  Top Layer w40: P4.6@108,3329 P5.6@208.4,3329 ; P5.6@222.4,3315 285.16,3315 R9.2@301.82,3298.33
  Bottom Layer w15: 1098.75,3888 v1(1114,3888)
  Bottom Layer w20: P5.6@209,3329 270,3329 302,3361 459,3361 502,3404 502,3795 595,3888 v1(1114,3888)
  Bottom Layer w40: 270,3329 271.16,3329 R10.2@301.82,3298.33
  Bottom Layer w50: P4.6@108,3329 P5.6@209,3329
Cell6: D8.2 P4.7 P5.7 Q7.2 R22.2 R23.2 R31.1 | length 1107.8
  Top Layer w15: P4.7@108.22,3428.78 R22.2@289.46,3428.78 ; Q7.2@484,3498.13 607.51,3498.13 D8.2@626,3516.63 R31.1@675.31,3516.63
  Top Layer w20: P5.7@209,3429 209,3462 229.08,3482.08 455.77,3482.08 471.82,3498.13 Q7.2@484,3498.13
  Top Layer w40: P4.7@108,3429 P5.7@209,3429 R22.2@301.41,3429
  Bottom Layer w15: R23.2@289.24,3429 R23.2@301.82,3416.42
  Bottom Layer w50: P4.7@108,3429 P5.7@209,3429 289.24,3429 R23.2@301.41,3429
Cell7: D9.2 P4.8 P5.8 Q8.2 R24.2 R25.2 R32.1 | length 1173.7
  Top Layer w15: P4.8@108.22,3528.78 R24.2@296.1,3528.78 ; Q8.2@484,3615.61 608.09,3615.61 D9.2@626,3633.52 R32.1@675.12,3633.52
  Top Layer w20: P5.8@209,3529 209,3550 254,3595 448,3595 468.61,3615.61 Q8.2@484,3615.61
  Top Layer w40: P4.8@108,3529 P5.8@209,3529 R24.2@296.32,3529
  Bottom Layer w15: P5.8@208.63,3528.78 R25.2@296.1,3528.78
  Bottom Layer w50: P4.8@108,3529 P5.8@209,3529 R25.2@296.32,3529
Cell8: D10.2 P4.9 P5.9 Q9.2 R26.2 R27.2 R33.1 | length 825.7
  Top Layer w15: Q9.2@484,3733.09 608.67,3733.09 D10.2@626,3750.42 638.99,3737.42 R33.1@679.51,3737.42
  Top Layer w20: R26.2@301.91,3650 357.91,3706 446,3706 469.6,3729.6 Q9.2@483.76,3729.6
  Top Layer w40: P4.9@108,3629 208.4,3629 231.99,3652.58 R26.2@301.82,3652.58
  Bottom Layer w15: R27.2@291.24,3652.58 R27.2@301.82,3652.58
  Bottom Layer w50: P4.9@108,3629 P5.9@209,3629 222,3642 R27.2@291.24,3642
Cell9: D12.2 P4.10 P5.10 Q10.2 R28.2 R29.2 R34.1 R50.1 R64.1 | length 2426.8
  Top Layer w20: Q10.2@484,3850.57 492.43,3859 D12.2@617.69,3859 ; Q10.2@495.43,3850.57 512,3834 667.79,3834 R34.1@679.51,3845.72 ; D12.2@632.69,3874 646,3874 671.87,3899.87 R50.1@679.51,3899.87
  Top Layer w30: R28.2@300.91,3763 300.91,3769.76 300.91,3792.91 335,3827 448.62,3827 472.19,3850.57 Q10.2@484,3850.57
  Top Layer w40: P4.10@108,3729 P5.10@209,3729 260.16,3729 R28.2@300.91,3769.76
  Bottom Layer w20: R29.2@301.82,3770.67 301.82,3783.82 348,3830 489,3830 630,3971 1137,3971 1392,3716 v1(1392,3624)
  Bottom Layer w50: P4.10@108,3729 P5.10@209,3729 260.16,3729 R29.2@301.82,3770.67
Cell10: D13.2 P4.11 P5.11 Q11.2 R39.2 R40.2 R51.1 | length 856.4
  Top Layer w15: Q11.2@484,3968.04 609.84,3968.04 D13.2@626,3984.21 626,3988.09 659.44,3988.09 R51.1@679.51,4008.16
  Top Layer w20: R39.2@301.82,3911.82 338,3948 455.97,3948 476.01,3968.04 Q11.2@484,3968.04
  Top Layer w40: P4.11@108,3829 P5.11@208.4,3829 ; P5.11@209,3829 252,3872 276,3872 292.75,3888.75 R39.2@301.82,3888.75
  Bottom Layer w50: P4.11@108,3829 P5.11@209,3829 242.07,3829 R40.2@301.82,3888.75
Cell11: D14.2 P4.12 P5.12 Q12.2 R41.2 R42.2 R52.1 | length 873.9
  Top Layer w15: R41.2@294.03,3999.04 R41.2@301.82,4006.83 ; Q12.2@484,4085.52 610.42,4085.52 D14.2@626,4101.1 631.99,4101.1 647.35,4116.46 R52.1@679.51,4116.46
  Top Layer w20: R41.2@301.82,4006.83 301.82,4019.82 347,4065 450,4065 470.52,4085.52 Q12.2@484,4085.52
  Top Layer w40: P4.12@108,3929 208.4,3929 R41.2@286.24,4006.83
  Bottom Layer w15: R42.2@294.33,3999.34 R42.2@301.82,4006.83
  Bottom Layer w50: P4.12@108,3929 P5.12@209,3929 R42.2@286.83,4006.83
Cell12: D15.2 P4.13 P5.13 Q13.2 R43.2 R44.2 R53.1 | length 881.3
  Top Layer w15: P5.13@208.63,4028.78 P5.13@208.63,4029 ; R43.2@300.57,4123.67 R43.2@301.82,4124.92 ; Q13.2@476.45,4202.56 476.9,4203 Q13.2@484,4203 611,4203 D15.2@626,4218 R53.1@672.75,4218
  Top Layer w20: R43.2@301.82,4124.92 359.91,4183 448,4183 468,4203 Q13.2@476.01,4203
  Top Layer w40: P4.13@108,4029 208.4,4029 R43.2@301.82,4122.42
  Bottom Layer w15: R44.2@300.28,4123.37 R44.2@301.82,4124.92
  Bottom Layer w30: P5.13@209,4029 301.82,4121.82 R44.2@301.82,4124.92
  Bottom Layer w50: P4.13@108,4029 P5.13@209,4029
Cell13: C18.2 D47.1 P4.14 P5.14 Q16.2 Q26.2 R45.2 R46.2 R48.1 R54.1 R65.1 R69.1 R123.2 | length 5682.1
  Top Layer w20: P5.14@219,4139 R54.1@219,4208.5 253.5,4243 R45.2@301.82,4243 ; R123.2@1095.5,4280.5 1128,4313 1198,4313 1223.6,4287.4 Q26.2@1223.6,4277.24 ; Q16.2@1501.6,3601.24 1501.6,3651.09 R69.1@1505.5,3655
  Top Layer w40: P4.14@108,4129 P5.14@209,4129 ; 162,4132 162,4325 187,4350 897.44,4350 D47.1@1043.53,4203.91 ; R48.1@1037.81,4109.42 1037.81,4198.19 D47.1@1043.53,4203.91 ; D47.1@1043.53,4202 D47.1@1043.53,4203.91 ; R123.2@1095.5,4273 1043.53,4221.03 D47.1@1043.53,4203.91
  Bottom Layer w12: 1430.21,3629.79 v1(1492,3629.79)
  Bottom Layer w15: 1143.28,4003.72 1164.06,4024.5 1932.5,4024.5 2071,3886 2071,2969 v1(2007,2905)
  Bottom Layer w20: R46.2@301.82,4243 240.7,4243 209,4211.3 P5.14@209,4129 264,4184 514,4184 694.28,4003.72 1143.28,4003.72 1430,3717 1430,3583 v1(1402,3555)
CEN: R89.1 U3.12 U5.4 | length 1160.3
  Top Layer w11: v1(2447,3228) 2581.96,3228 2656,3153.96 2656,2842.5 R89.1@2725,2773.5 2725,2780 U5.4@2787.05,2780
  Top Layer w12: v1@2112,3377 2112.37,3377.37 U3.12@2158.14,3377.37
  Bottom Layer w12: v1@2112,3377 2261,3228 v1(2447,3228)
  other v1: 2110,3389
Charge_Pump: R97.1 U3.33 | length 1321.2
  Top Layer w10: U3.33@1925.86,3259.26 1888.23,3259.26 1866,3237.03 1866,3077 1790,3001 1790,2940 1745,2895 1745,2717 1764.25,2697.75 1764.25,2304.75 R97.1@1946.4,2122.6 ; R97.1@1943.79,2119.99 1946.4,2117.39 R97.1@1946.4,2116.94
CHG: R99.1 U1.2 | length 1776
  Top Layer w10: v1(1163,3136) 1172.86,3145.86 U1.2@1263.98,3145.86 ; v1(1772,2880) 1763,2871 1763,2722 1782.13,2702.87 1782.13,2335.16 1999.9,2117.39 R99.1@1999.9,2116.94
  Bottom Layer w10: v1(1163,3136) 1171,3144 1234,3144 1244,3134 1600,3134 1687,3047 1687,2903 1710,2880 v1(1772,2880)
CHG_G: D34.1 D36.1 L2.1 L3.1 L4.1 Q22.2 R105.1 | length 1278
  Top Layer w20: Q22.2@1057.76,1096.24 991.5,1162.5 979,1162.5 979,1163.47 D36.1@909,1233.47 971.03,1295.5 L3.1@1017,1295.5 1037.5,1316 D34.1@1097.53,1316
  Top Layer w25: v1(1068,523) 1079,512 L4.1@1079,494.5 ; v1(1068,954) 1079,943 L2.1@1079,924.5
  Bottom Layer w20: v1(1056,1300) 1068,1288 v1(1068,954) v1(1068,523)
CHG_S: C68.2 D36.2 F1.3 F2.1 Q22.3 Q28.3 Q29.3 Q30.3 R103.2 R105.2 | length 1021.2
  Top Layer w20: 1263,53 2271.5,53 C68.2@2280.5,62
Commu_EN: J5.1 U5.1 | length 382.3
  Top Layer w20: U5.1@3042.95,2780 3397,2780 J5.1@3417,2760
DCHG: R96.1 U1.1 | length 1580.5
  Top Layer w10: v4(1200,3118) 1255.8,3118 U1.1@1263.98,3126.18 ; v1(1714,2848) 1714,2725 1746.38,2692.62 1746.38,2271.62 R96.1@1892.9,2125.1 ; R96.1@1889.04,2121.24 1892.9,2117.39 R96.1@1892.9,2116.94
  Bottom Layer w10: v4(1200,3118) 1588,3118 1671,3035 1671,2891 v1(1714,2848)
DCHG_G: D40.1 L5.2 L6.2 L7.2 Q23.3 R109.2 R110.1 | length 1377.6
  Top Layer w20: 2197.4,1380 Q23.3@2222,1355.4
  Top Layer w25: v1(2350,676) 2362.5,663.5 L6.2@2362.5,652
  Top Layer w30: R110.1@2308.5,1150 D40.1@2382.47,1150 ; L7.2@2360.57,1083 D40.1@2360.57,1147.43
  Bottom Layer w20: v1(2195,1363) 2350,1208 v1(2350,1113) v1(2350,676) v1(2350,252)
EN: Q20.1 U3.18 | length 946.8
  Top Layer w10: U3.18@2158.14,3495.48 2207.48,3495.48 v1(2224,3512) ; v1(2224,3659) 2224,3707 2302.5,3785.5 2460.5,3785.5 2628,3953 2628,3985 2730.4,4087.4 Q20.1@2738.76,4087.4
  Bottom Layer w10: v1@2224,3524 v1(2224,3659)
F_CON: Q27.1 U3.23 | length 572.1
  Top Layer w10: Q27.1@1758.6,3865.6 1758.6,3874.76 1743,3859.16 1743,3608.91 1782,3569.91 1782,3494 1819.89,3456.11 U3.23@1925.86,3456.11
GND: C1.2 C2.2 C13.2 C19.2 C21.2 C24.1 C29.2 C30.2 C31.1 C32.2 C33.1 C34.2 C35.2 C36.2 C37.2 C38.2 C39.1 C40.2 C42.2 C44.2 C48.2 C50.2 C51.2 C52.2 C54.2 C55.2 C57.1 C58.2 C59.2 C61.1 C62.2 C66.2 C67.2 D1.2 D28.2 D29.2 D35.2 D44.2 J1.1 J1.2 J1.3 J1.4 J1.5 J1.6 P2.4 P3.3 P3.4 P6.2 Q17.2 Q20.2 Q21.2 Q24.2 Q25.2 Q27.2 R60.1 R73.1 R76.1 R77.1 R78.1 R79.1 R80.1 R102.1 R116.1 R117.1 R118.1 R119.1 R121.1 R124.1 R125.2 R130.1 RT1.1 S2.2 U1.3 U2.1 U2.5 U3.11 U4.3 U4.8 U4.12 U5.3 U6.2 U7.3 U8.4 U8.5 U9.4 U10.1 U10.5 U14.8 U14.9 U15.1 U15.9@1897,4175 | length 8376.1
  Top Layer w10: 1225,2534 v1(1317,2534) 1329,2546 1329,2678.63 1367.37,2717 1392,2717 1399.33,2724.33 R124.1@1399.33,2774.5
  Top Layer w11: C1.2@861.5,2816 C2.2@861.5,2868.5 ; U1.3@1263.98,3165.55 1309.55,3165.55 C21.2@1317,3173
  Top Layer w12: U3.11@2158.14,3357.69 2163.91,3357.69 2165.69,3359.46 2187.21,3359.46 C33.1@2235,3407.25
  Top Layer w15: D1.2@772.47,2759 804.5,2759 C1.2@861.5,2816 ; 1097.5,3165.5 U1.3@1263.98,3165.55 ; 1820.24,1952.4 1843.26,1975.41 U14.8@1889.33,1975.41 ; 1995.09,2216 2060.09,2151 2160,2151 2206,2105 2206,1960.5 R102.1@2195,1949.5 ; C42.2@2893.18,3917.32 U8.5@2893.18,3970.6 U8.4@2893.18,4045.4
  Top Layer w18: v1(1653,3344) 1669.99,3327.01 U4.3@1669.99,3218.17 ; C34.2@2015.77,3910.13 2030.05,3924.4 U2.1@2076,3924.4
  Top Layer w20: 800,423 887.5,423 C54.2@927.5,463 929.4,464.91 Q24.2@929.4,514.76 ; v1(913,2912) R117.1@913,2946.44 ; C48.2@2119.9,1885.71 2125.71,1885.71 2153.02,1913.02 ; 2127,1913.02 2153.02,1913.02 ; R102.1@2195,1949.5 2158.52,1913.02 2153.02,1913.02
  Top Layer w25: 1145,3315 1145,3487 1066,3566 1066,3566.11 1064.5,3567.61 1064.5,3938.5 1081,3955 1269.09,3955 C24.1@1341.09,3883 ; v1(1820,2771) 1828,2763 1828,2375 2011.37,2191.63 ; 1820.24,1952.4 1886.65,1886 v1(2101,1886) ; U8.5@2893.18,3970.6 v1(2810.6,3970.6) 2780,3940 2780,3789 2805.5,3763.5 C40.2@2819,3763.5 2820.09,3764.6 U10.5@2865.87,3764.6 U10.1@2974.13,3764.6 3015.09,3764.6 C44.2@3021,3770.5
  Top Layer w30: v1(1864,1798) 1884,1778 C51.2@1884,1474.5 ; P2.4@2468,3618 2468,3687.53 D28.2@2493.47,3713
  Top Layer w40: R76.1@2617.5,2718 R77.1@2617.5,2821.75 R78.1@2617.5,2925.5 R79.1@2617.5,3029.25 R80.1@2617.5,3133
  Top Layer w100: R119.1@1192,2651 1192,2786.38
  Bottom Layer w10: v1(913,2912) 940,2885 1241.37,2885 1329,2797.37 1329,2546 v1(1317,2534)
  Bottom Layer w25: 1605,3835 RT1.1@1605,3893.47 ; v1(1864,1798) 1910,1844 2059,1844 v1(2101,1886)
  Bottom Layer w35: 51,4055 51,2782 116,2717 560,2717
  other v1: 1042,1720 1074,1720 1106,1720 1138,1720 1042,1752 1074,1752 1106,1752 1138,1752 1042,1784 1074,1784 1106,1784 1138,1784 1042,1816 1074,1816 1106,1816 1138,1816 1042,1848 1074,1848 1106,1848 1138,1848 1042,1880 1074,1880 1106,1880 1138,1880 1042,1912 1074,1912 1106,1912 1138,1912 1042,1944 1074,1944 1106,1944 1138,1944 1042,1976 1074,1976 1106,1976 1138,1976 1042,2008 1074,2008 1106,2008 1138,2008 1042,2040 1074,2040 1106,2040 1138,2040 1042,2072 1074,2072 1106,2072 1138,2072 1042,2104 1074,2104 1106,2104 1138,2104 1042,2136 1074,2136 1106,2136 1138,2136 1042,2168 1074,2168 1106,2168 1138,2168 1042,2200 1074,2200 1106,2200 1138,2200 1042,2232 1074,2232 1106,2232 1138,2232 1042,2264 1074,2264 1106,2264 1138,2264 1042,2296 1074,2296 1106,2296 1138,2296 1042,2328 1074,2328 1106,2328 1138,2328 1042,2360 1074,2360 1106,2360 1138,2360 1042,2392 1074,2392 1106,2392 1138,2392 1042,2424 1074,2424 1106,2424 1138,2424 1042,2456 1074,2456 1106,2456 1138,2456 1042,2488 1074,2488 1106,2488 1138,2488 1042,2520 1074,2520 1106,2520 1138,2520 1042,2552 1074,2552 1106,2552 1138,2552 1042,2584 1074,2584 1106,2584 1138,2584 1042,2616 1074,2616 1106,2616 1138,2616 1042,2648 1074,2648 1106,2648 1138,2648 986,2721 1014,2721 1042,2721 1070,2721 1098,2721 1126,2721 1154,2721 1182,2721 1450,2738 1480.5,2738 1511,2738 1000,2746 1028,2746 1056,2746 1084,2746 1112,2746 1140,2746 1168,2746 2623,2770.5 2800,2853 2623,2874 2623,2977.5 2717,3031 2744,3031 2115,3057 2703,3060 2730,3060 2757,3060 2623,3081 2115,3089 2104,3281 2700,3294 2647,3308 2675,3308 2700,3322 2259,3448 2351,3450 2232,3464 2258,3481 2289,3481 2320,3481 2351,3481 1697,3536 1695,3566 2790,3579 2805,3704 2822,3727 2792,3729 2162,3738 1803,3882 1865,3882 2283,3909 1818,3910 1846,3910 2283,3940 2837,3963 2185,3968 2212.71,3968 2240.43,3968 2268.14,3968 2295.86,3968 2323.57,3968 2351.29,3968 2379,3968 2829,3992 2852,4010 2722,4041 2755,4041 1763,4289 1795,4289 1827,4289 1859,4289 1891,4289 1923,4289 1763,4321 1795,4321 1827,4321 1859,4321 1891,4321 1763,4353 1795,4353 1827,4353 1859,4353 1891,4353
  other v2: 1875.35,4098.23 1918.65,4098.23 1875.35,4251.77 1918.65,4251.77
  other v3: 1875.35,4149.41 1918.65,4149.41 1875.35,4200.59 1918.65,4200.59
LED1: D23.2 U3.1 | length 638.2
  Top Layer w10: U3.1@2158.14,3160.83 2332.2,3160.83 2466,3027.04 2466,2816.5 D23.2@2511.5,2771
LED2: D24.2 U3.2 | length 556.1
  Top Layer w10: U3.2@2158.14,3180.52 2335.15,3180.52 2482,3033.67 2482,2904 D24.2@2511.5,2874.5
LED3: D25.2 U3.3 | length 472.9
  Top Layer w11: U3.3@2158.14,3200.2 2338.8,3200.2 2510.47,3028.53 D25.2@2510.47,2979.03
LED4: D26.2 U3.4 | length 409.7
  Top Layer w11: U3.4@2158.14,3219.89 2372.08,3219.89 D26.2@2510.47,3081.5
LED5: D27.2 U3.5 | length 376
  Top Layer w11: U3.5@2158.14,3239.57 2383.43,3239.57 2438,3185 D27.2@2511.5,3185
NetC18_1: C18.1 D16.2 Q15.1 R59.1 | length 213.6
  Top Layer w25: C18.1@1893,2928 1889.02,2924.02 D16.2@1889.02,2861.47 1899.48,2851 R59.1@1971.52,2851 1966.77,2846.25 Q15.1@1966.77,2794.4
NetC20_1: C20.1 R62.2 R67.2
NetC20_2: C20.2 Q15.3 R62.1 | length 170.9
  Top Layer w20: Q15.3@2061.26,2757 2087,2757 C20.2@2120.09,2723.91 ; C20.2@2159.02,2723.91 2252.59,2723.91 R62.1@2256,2720.5
NetC27_1: C27.1 RT2.1 U1.13 | length 733
  Top Layer w10: C27.1@1404,3370 1418,3370 1448,3400 1448,3729 1502,3783 1502,3833 1548,3879 RT2.1@1548,3893.47 ; RT2.1@1548.5,3879.69 RT2.1@1548.5,3882.47
  Top Layer w11: U1.13@1263.98,3362.4 C27.1@1402.9,3362.4
NetC28_1: C28.1 RT3.1 U1.18 | length 595.4
  Top Layer w11: U1.18@1263.98,3460.82 1381.33,3460.82 C28.1@1404,3483.5 1431.5,3511 1431.5,3735.83 1479,3783.33 1479,3881.47 RT3.1@1491,3893.47
NetC36_1: C36.1 R74.2 U4.5 U4.6 | length 318.3
  Top Layer w15: C36.1@1593.22,3284 U4.6@1593.22,3218.17 ; U4.5@1618.81,3218.17 U4.6@1593.22,3218.17 ; R74.2@1772,3199.5 1745.5,3173 1607,3173 1593.22,3186.78 U4.6@1593.22,3218.17
NetC40_1: C40.1 C42.1 Q19.3 T1.2 U8.2 U10.2 U10.4 | length 586.2
  Top Layer w20: Q19.3@2830.24,3921 2819,3909.76 2819,3871 ; C42.1@2952,3921.5 2952,3981 2979,4008 U8.2@3001.45,4008 ; C42.1@2961.5,3912 2920.5,3871 2819,3871 ; U10.2@2974.13,3802 2903.27,3802 U10.4@2865.87,3839.4 2829.6,3839.4 2819,3850 2819,3871 ; U8.2@3002.45,4007 T1.2@3058.39,4007
NetC45_2: C45.2 R92.1 R93.2
NetC46_1: C46.1 D30.1 D31.1 U12.2 U12.4 | length 535.2
  Top Layer w20: U12.2@3391.87,3660 3441,3660 3478.4,3622.6 U12.4@3500.13,3622.6 3554,3676.46 3554,3751 C46.1@3539,3766 D31.1@3539,3852.53 ; D30.1@3526,3992.53 3539.47,3992.53 D31.1@3539.47,3853
NetC48_1: C48.1 C49.2 R98.1 U14.2 | length 450.4
  Top Layer w11: C49.2@2042.87,2029.18 C49.2@2060.9,2047.21 C49.2@2060.9,2059.4
  Top Layer w15: C49.2@2042.87,2029.18 U14.2@2042.87,1975.41 2042.87,1952.13 2058.52,1936.48 2107.67,1936.48 C48.1@2119.9,1948.7 2185,2013.81 2185,2092 2160,2117 R98.1@2118.5,2117
NetC49_1: C49.1 U14.1 | length 92.3
  Top Layer w11: U14.1@2071.08,1993 2086.69,1993 C49.1@2140.9,2047.21
NetC51_1: C51.1 R113.2 R115.1 | length 120.7
  Top Layer w20: C51.1@1884,1411.5 R113.2@1939,1411.5 1953.5,1426 1989.5,1426 R115.1@1996,1432.5
NetC52_1: C52.1 C53.2 | length 57
  Top Layer w20: C53.2@400,1391.5 C52.1@400,1448.5
NetC54_1: C54.1 P3.1 P3.2 Q24.1 R116.2 | length 113.7
  Top Layer w20: R116.2@802,527.5 841.86,527.5 Q24.1@854.6,514.76 854.6,472.91 C54.1@864.5,463
NetC62_1: C62.1 R128.1 | length 57
  Top Layer w20: C62.1@1982.5,4329 R128.1@2039.5,4329
NetC63_1: C63.1 U15.7 | length 57.2
  Top Layer w25: U15.7@2004.28,4200 C63.1@2061.5,4200
NetC63_2: C63.2 L1.1 R128.2 R129.1 U15.8 | length 245.5
  Top Layer w25: U15.8@2004.28,4250 2053.5,4250 C63.2@2065,4261.5 ; 2102.5,4256.5 R128.2@2102.5,4329 ; R129.1@2119,4138 L1.1@2166.83,4138 ; L1.1@2169.3,4215.7 2195.83,4189.17 L1.1@2195.83,4167
NetC64_1: C64.1 C65.1 R129.2
NetC64_2: C64.2 R130.2 R131.1 U15.5 | length 205.6
  Top Layer w20: R130.2@1980.5,4045 2004.28,4068.79 U15.5@2004.28,4100 2022,4100 2060,4138 C64.2@2065,4138
  Top Layer w25: R131.1@1960.5,3989 1980.5,4008.99 R130.2@1980.5,4045
NetC68_1: C68.1 C69.2 | length 56.1
  Top Layer w35: C68.1@2343.5,62 2345,63.5 C69.2@2399,63.5
NetC70_1: C70.1 C71.2 | length 85
  Top Layer w20: C71.2@3188,1295.5 C70.1@3188,1380.5
NetD2_1: D2.1 Q1.1 R17.1 | length 204.6
  Top Layer w15: Q1.1@484,2868.07 616.48,2868.07 D2.1@626,2858.56 638.49,2871.05 R17.1@679.51,2871.05
NetD3_1: D3.1 Q2.1 R18.1 | length 195.8
  Top Layer w15: Q2.1@484,2985.55 615.9,2985.55 D3.1@626,2975.46 R18.1@675.62,2975.46
NetD4_1: D4.1 Q3.1 R19.1 | length 195.2
  Top Layer w15: Q3.1@484,3103.03 615.32,3103.03 D4.1@626,3092.35 R19.1@674.81,3092.35
NetD5_1: D5.1 Q4.1 R20.1 | length 205.7
  Top Layer w15: Q4.1@484,3220.5 614.74,3220.5 D5.1@626,3209.25 631.99,3209.25 645.3,3195.94 R20.1@679.51,3195.94
NetD6_1: D6.1 Q5.1 R21.1 | length 210.6
  Top Layer w15: Q5.1@484,3337.98 614.16,3337.98 D6.1@626,3326.14 626,3324.31 659.44,3324.31 R21.1@679.51,3304.24
NetD7_1: D7.1 Q6.1 R35.1 | length 210.5
  Top Layer w15: Q6.1@484,3455.46 613.57,3455.46 D7.1@626,3443.04 649.64,3466.68 R35.1@679.51,3466.68
NetD8_1: D8.1 Q7.1 R36.1 | length 207.1
  Top Layer w15: Q7.1@484,3572.94 613,3572.94 D8.1@626,3559.93 641.05,3574.98 R36.1@679.51,3574.98
NetD9_1: D9.1 Q8.1 R37.1 | length 194.7
  Top Layer w15: Q8.1@484,3690.42 612.41,3690.42 D9.1@626,3676.83 R37.1@673.06,3676.83
NetD10_1: D10.1 Q9.1 R38.1 | length 199.2
  Top Layer w15: Q9.1@484,3807.89 611.83,3807.89 D10.1@626,3793.72 R38.1@677.36,3793.72
NetD11_2: D11.2 Q14.2 R49.1 | length 114.4
  Top Layer w20: Q14.2@1236.71,4024.18 1280.35,4024.18 1299.5,4043.33 R49.1@1299.5,4087
NetD12_1: D12.1 Q10.1 R55.1 | length 209.5
  Top Layer w15: Q10.1@484,3925.37 611.25,3925.37 D12.1@626,3910.62 R55.1@669.4,3954.02
NetD13_1: D13.1 Q11.1 R56.1 | length 216.3
  Top Layer w15: Q11.1@484,4042.85 610.67,4042.85 D13.1@626,4027.52 649.48,4051 668.2,4051 R56.1@679.51,4062.31
NetD14_1: D14.1 Q12.1 R57.1 | length 213
  Top Layer w15: Q12.1@484,4160.33 610.09,4160.33 D14.1@626,4144.41 652.2,4170.61 R57.1@679.51,4170.61
NetD15_1: D15.1 Q13.1 R58.1 | length 209.6
  Top Layer w15: Q13.1@484,4277.8 609.5,4277.8 D15.1@626,4261.31 643.6,4278.91 R58.1@679.51,4278.91
NetD19_1: D19.1 D21.1 D22.2 R66.2 R67.1 | length 221.7
  Top Layer w20: D22.2@2202.65,2920 R67.1@2254,2920 ; R67.1@2254,2910.5 R67.1@2262.5,2910.5 ; R66.2@2315.65,2912.84 D19.1@2315.65,2971 ; R66.2@2324.81,2919.31 D21.1@2374,2919.31
  Top Layer w40: R67.1@2262.5,2911.5 R66.2@2317,2911.5
NetD19_2: D19.2 R61.1 | length 60.9
  Top Layer w23: R61.1@2211.5,2971 D19.2@2272.35,2971
NetD23_1: D23.1 R76.2 | length 61.3
  Top Layer w20: R76.2@2554.5,2718 2554.5,2751.01 D23.1@2574.5,2771
NetD24_1: D24.1 R77.2 | length 61
  Top Layer w20: R77.2@2554.5,2821.75 2554.5,2854.51 D24.1@2574.5,2874.5
NetD25_1: D25.1 R78.2 | length 60.8
  Top Layer w20: R78.2@2554.5,2925.5 2554.5,2958.01 D25.1@2574.5,2978
NetD26_1: D26.1 R79.2 | length 60.5
  Top Layer w20: R79.2@2554.5,3029.25 2554.5,3061.51 D26.1@2574.5,3081.5
NetD27_1: D27.1 R80.2 | length 60.3
  Top Layer w20: R80.2@2554.5,3133 2554.5,3165.01 D27.1@2574.5,3185
NetD28_1: D28.1 P2.3 R84.2 | length 359.8
  Top Layer w11: P2.3@2368,3618 2368,3716 2404,3752 2509.5,3752 R84.2@2584,3826.5
NetD29_1: D29.1 P2.2 R85.2 | length 534.2
  Top Layer w11: P2.2@2268,3618 2290.47,3640.47 D29.1@2290.47,3713 2346.47,3769 2478,3769 2559.8,3850.8 2559.8,3850.94 2566.54,3857.68 2566.68,3857.68 2568,3859 2614,3859 2646,3827 R85.2@2646,3826.5
NetD30_2: D30.2 T1.6 | length 106
  Top Layer w20: T1.6@3418.24,4107 3427.24,4116 D30.2@3520.53,4116
NetD31_2: D31.2 T1.4 | length 46.3
  Top Layer w20: D31.2@3410.53,3853 T1.4@3410.53,3899.3
NetD33_1: D33.1 D34.2 Q22.1 R103.1 | length 389
  Top Layer w20: Q22.1@1057.76,1170.4 1201.91,1170.4 R103.1@1206,1174.5 1226.47,1194.96 D34.2@1226.47,1316 ; D34.2@1222.53,1319.94 D33.1@1222.53,1409
NetD33_2: D33.2 R100.2 | length 66
  Top Layer w20: D33.2@1351.47,1409 R100.2@1351.47,1475.04
NetD38_1: D38.1 R107.1 | length 70
  Top Layer w11: R107.1@2076.5,1592 D38.1@2076.5,1661.97
NetD38_2: D38.2 R111.1 U14.11 | length 156.8
  Top Layer w11: R111.1@1940,1591.5 1940,1658.47 D38.2@1945.53,1664 ; D38.2@1940.51,1669.02 U14.11@1940.51,1751
NetD39_1: D39.1 R108.2 R109.1 | length 150.8
  Top Layer w11: D39.1@2202.47,1454.53 D39.1@2208,1454.53
  Top Layer w20: R109.1@2108,1393.5 R108.2@2108,1441 2116,1449 D39.1@2202.47,1449
NetD41_1: D41.1 R111.2 R113.1 | length 127
  Top Layer w11: R111.2@1940,1513 R111.2@1940,1528.5
  Top Layer w20: R113.1@1940,1475.5 1940,1513 2012.53,1513 D41.1@2013.53,1512
NetD42_1: D42.1 D43.1 Q23.1 R114.2 | length 318.6
  Top Layer w15: Q23.1@2196.41,1280.6 2269.31,1353.5 R114.2@2299,1353.5
  Top Layer w20: R114.2@2299,1353.5 2299,1451.4 D42.1@2301.07,1453.47 ; D42.1@2300,1454.54 D42.1@2301.07,1453.47 ; D43.1@2381.47,1446 2308.54,1446 D42.1@2301.07,1453.47
NetD42_2: D42.2 R112.2 | length 68.5
  Top Layer w20: R112.2@2261.5,1636 2261.5,1624.5 2300,1586 D42.2@2300,1583.48
NetD45_1: D45.1 D46.1 Q25.1 R121.2 | length 220.1
  Top Layer w20: Q25.1@1471.4,4276.24 R121.2@1521.65,4226 ; D46.1@1502,4155.47 D45.1@1585,4155.47 ; 1527.5,4159.96 R121.2@1527.5,4226
NetD47_2: D47.2 Q26.1 R122.2 R123.1 | length 245.1
  Top Layer w20: R123.1@1158.5,4273 1172.47,4259.03 1172.47,4229 1250.16,4229 Q26.1@1298.4,4277.24 ; Q26.1@1298.65,4277.5 R122.2@1348,4277.5
NetF1_2: F1.2 Q24.3 | length 48.3
  Top Layer w25: Q24.3@892,609.24 F1.2@892,657.51
NetL2_2: L2.2 Q29.1 | length 59.5
  Top Layer w35: Q29.1@1079,800 L2.2@1079,859.5
NetL3_2: L3.2 Q30.1 | length 104.6
  Top Layer w35: L3.2@1017,1232.5 1018.3,1231.21 Q30.1@1121.09,1231.21
NetL4_2: L4.2 Q28.1 | length 57.8
  Top Layer w35: Q28.1@1079,369.73 L4.2@1079,427.5
NetL5_1: L5.1 Q32.1 | length 51.6
  Top Layer w35: Q32.1@2297.58,171.42 L5.1@2297.58,223
NetL6_1: L6.1 Q33.1 | length 30.3
  Top Layer w35: Q33.1@2297.58,616.73 L6.1@2297.58,647
NetL7_1: L7.1 Q34.1 | length 51.6
  Top Layer w35: Q34.1@2297.58,1031.42 L7.1@2297.58,1083
NetQ1_3: Q1.3 R1.1 R2.1 | length 157.8
  Top Layer w15: R1.1@420.66,2830.67 Q1.3@578.49,2830.67
  other v1: 371,2808 371,2843
NetQ2_3: Q2.3 R3.1 R4.1 | length 158.4
  Top Layer w15: R3.1@420.06,2948.15 Q2.3@578.49,2948.15
  other v1: 371,2930 371,2963
NetQ3_3: Q3.3 R5.1 R6.1 | length 159
  Top Layer w15: R5.1@419.45,3065.63 Q3.3@578.49,3065.63
  other v1: 371,3048 371,3083
NetQ4_3: Q4.3 R7.1 R8.1 | length 159.6
  Top Layer w15: R7.1@418.85,3183.1 Q4.3@578.49,3183.1
  other v1: 371,3164 371,3198
NetQ5_3: Q5.3 R9.1 R10.1 | length 160.2
  Top Layer w15: R9.1@418.24,3300.58 Q5.3@578.49,3300.58
  other v1: 371,3282 371,3311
